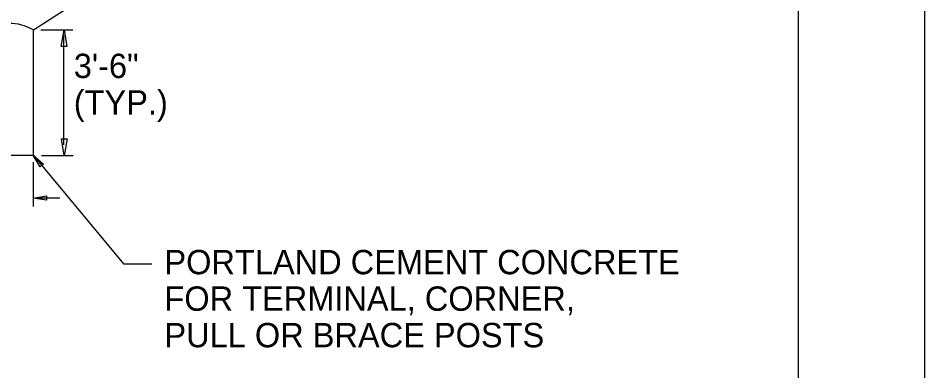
# Model space of a CAD drawing. Extents: x 0 to 2.85, y -0.1 to 1.83.
# Drawn here: x 2.4608 to 2.8333, y 0.6655 to 0.8104 of the extents above; entities that cross this region are included whole.
import ezdxf

# ---------------------------------------------------------------- set-up
doc = ezdxf.new("R2010")
doc.units = 0
for name, color, linetype in [('BDR_Inner_Perimeter', 7, 'Continuous'), ('BDR_Outer_Perimeter', 7, 'Continuous'), ('CT_Dimensions', 7, 'Continuous'), ('sb_Chainlink Fence', 7, 'Continuous'), ('sb_Existing Concrete', 7, 'Continuous')]:
    doc.layers.add(name, color=color, linetype=linetype)

msp = doc.modelspace()

# ---------------------------------------------------------------- linework, layer by layer
at = {"layer": 'BDR_Inner_Perimeter'}
msp.add_lwpolyline([(0.1353943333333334, 1.781248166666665), (2.7812276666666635, 1.781248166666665), (2.7812276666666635, 0.052081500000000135), (0.1353943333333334, 0.052081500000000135)], close=True, dxfattribs=at)
at = {"layer": 'BDR_Outer_Perimeter'}
msp.add_lwpolyline([(0, 0), (2.8333276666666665, 0), (2.833327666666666, 1.8333296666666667), (0, 1.8333296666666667)], close=True, dxfattribs=at)
at = {"layer": 'CT_Dimensions'}
for p, q in [((2.4701087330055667, 0.8055907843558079), (2.483208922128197, 0.8055907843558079)), ((2.4796307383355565, 0.7583539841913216), (2.4796307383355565, 0.8033927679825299)), ((2.4670894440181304, 0.7539664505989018), (2.504072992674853, 0.7094392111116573)), ((2.470370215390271, 0.7540626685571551), (2.4833523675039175, 0.7540626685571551)), ((2.4670491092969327, 0.7331058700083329), (2.4670491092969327, 0.7512114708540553)), ((2.4687033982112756, 0.7365846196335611), (2.4779673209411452, 0.7365846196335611)), ((2.504072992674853, 0.7094392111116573), (2.5156916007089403, 0.7094727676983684))]:
    msp.add_line(p, q, dxfattribs=at)
for points in [[(2.478494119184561, 0.7987542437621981), (2.479637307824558, 0.8056133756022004), (2.4807804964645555, 0.7987542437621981)], [(2.48089278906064, 0.7608473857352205), (2.479749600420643, 0.753988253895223), (2.4786064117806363, 0.7608473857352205)], [(2.4697870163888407, 0.7492881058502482), (2.466957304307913, 0.7540885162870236), (2.4711909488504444, 0.7504653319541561)], [(2.4725075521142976, 0.7356188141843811), (2.467011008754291, 0.7365349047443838), (2.4725075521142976, 0.7374509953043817)]]:
    msp.add_lwpolyline(points, close=True, dxfattribs=at)
at = {"layer": 'sb_Chainlink Fence'}
msp.add_line((2.467098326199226, 0.8055926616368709), (2.668987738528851, 0.9357626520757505), dxfattribs=at)
at = {"layer": 'sb_Existing Concrete'}
for q in [(2.467098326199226, 0.8055926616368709), (2.4468792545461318, 0.7539664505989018)]:
    msp.add_line((2.4670894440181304, 0.7539664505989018), q, dxfattribs=at)
msp.add_arc((2.457048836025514, 0.7879651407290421), 0.020290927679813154, 60.31243611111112, 120.04705000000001, dxfattribs=at)

# ---------------------------------------------------------------- texts
at = {"layer": 'CT_Dimensions'}
for s, p in [(' 3\'-6"', (2.479936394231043, 0.7858118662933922)), (' (TYP.)', (2.479936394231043, 0.7708118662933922)), ('PORTLAND CEMENT CONCRETE', (2.5208913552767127, 0.7052180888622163)), ('FOR TERMINAL, CORNER, ', (2.5208913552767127, 0.6902180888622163)), ('PULL OR BRACE POSTS', (2.5208913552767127, 0.6752180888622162))]:
    msp.add_text(s, height=0.01, dxfattribs=at).set_placement(p)

doc.saveas('drawing.dxf')
